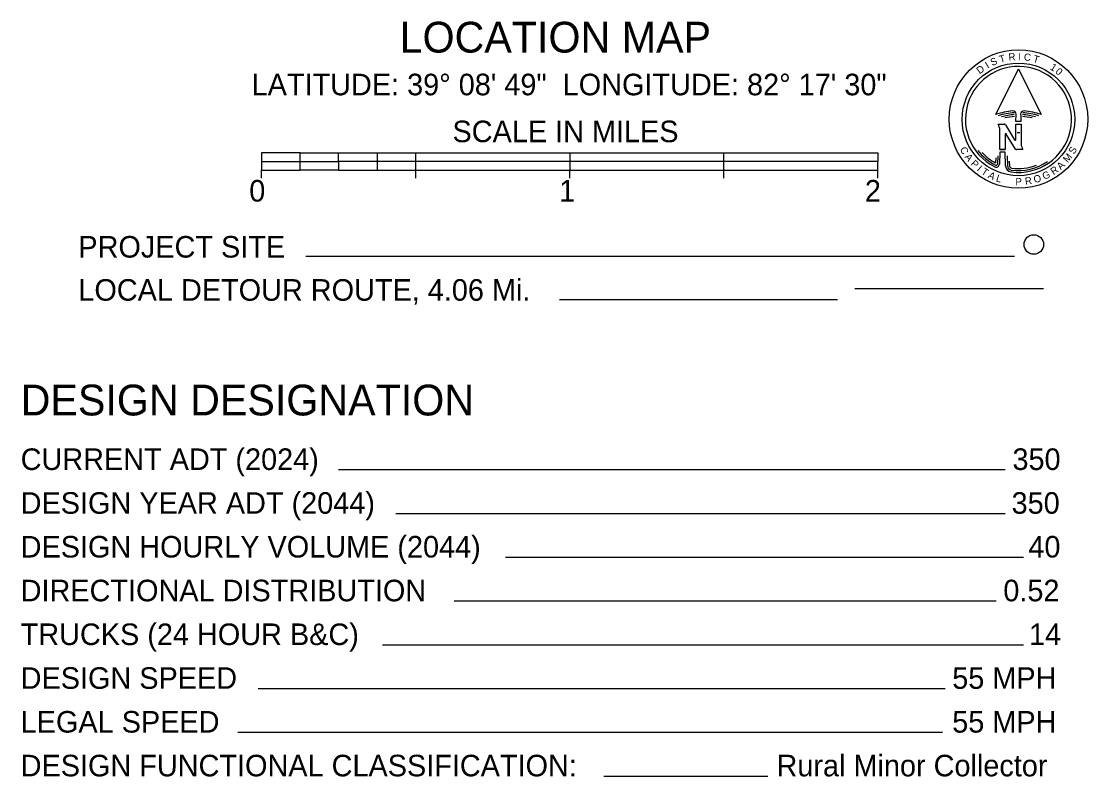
# Model space of a CAD drawing. Extents: x -15 to 405, y -40 to 87.
# Drawn here: x 32.612 to 36.073, y -34.788 to -32.337 of the extents above; entities that cross this region are included whole.
import ezdxf

# ---------------------------------------------------------------- set-up
doc = ezdxf.new("R2010")
doc.units = 0
for name, color, linetype in [('GM_P_State_Shield', 7, 'Continuous'), ('GM_X_Township', 7, 'Continuous'), ('GM_X_Township_ROW', 7, 'Continuous')]:
    doc.layers.add(name, color=color, linetype=linetype)

msp = doc.modelspace()

# ---------------------------------------------------------------- linework, layer by layer
at = {"layer": 'GM_P_State_Shield'}
msp.add_line((35.9294, -33.2052), (35.3172, -33.2052), dxfattribs=at)
at = {"layer": 'GM_X_Township'}
for p, q in [((35.7747, -32.639), (35.848, -32.4902)), ((35.848, -32.4902), (35.9212, -32.639)), ((35.8397, -32.6618), (35.8406, -32.6379)), ((35.856, -32.6618), (35.8397, -32.6618)), ((35.848, -32.6549), (35.848, -32.6549)), ((35.848, -32.6549), (35.848, -32.6549)), ((35.848, -32.6549), (35.848, -32.6549)), ((35.848, -32.6549), (35.848, -32.6549)), ((35.7816, -32.6701), (35.8025, -32.6701)), ((35.7878, -32.753), (35.7878, -32.6888)), ((35.806, -32.6721), (35.8355, -32.7208)), ((35.8394, -32.7198), (35.8394, -32.6701)), ((35.8394, -32.6701), (35.8564, -32.6701)), ((35.8564, -32.6701), (35.8564, -32.7344)), ((35.8048, -32.7034), (35.8048, -32.753)), ((35.8382, -32.7511), (35.8086, -32.7024)), ((35.8523, -32.6987), (35.8437, -32.6987)), ((33.5171, -32.7632), (33.3921, -32.7632)), ((33.3921, -32.7632), (33.3921, -32.7913)), ((33.5171, -32.7632), (33.6421, -32.7632)), ((33.5171, -32.7913), (33.5171, -32.7632)), ((33.6421, -32.7913), (33.6421, -32.7632)), ((33.6421, -32.7632), (33.7671, -32.7632)), ((33.7671, -32.7632), (33.8921, -32.7632)), ((33.7671, -32.7632), (33.7671, -32.7913)), ((33.8921, -32.7913), (33.8921, -32.7632)), ((33.8921, -32.7632), (34.3921, -32.7632)), ((34.3921, -32.7632), (34.8921, -32.7632)), ((34.3921, -32.7632), (34.3921, -32.7913)), ((34.8921, -32.7913), (34.8921, -32.7632)), ((34.8921, -32.7632), (35.3921, -32.7632)), ((35.3921, -32.7632), (35.3921, -32.7913)), ((35.7878, -32.7613), (35.786, -32.8001)), ((35.8048, -32.753), (35.7878, -32.753)), ((35.7878, -32.753), (35.8048, -32.753)), ((35.8048, -32.7613), (35.7878, -32.7613)), ((35.8061, -32.806), (35.8048, -32.7613)), ((35.8626, -32.753), (35.8417, -32.753)), ((33.3921, -32.7913), (33.3921, -32.8194)), ((33.3921, -32.7913), (33.5171, -32.7913)), ((33.5171, -32.7913), (33.6421, -32.7913)), ((33.5171, -32.8194), (33.5171, -32.7913)), ((33.6421, -32.7913), (33.6421, -32.8194)), ((33.7671, -32.7913), (33.6421, -32.7913)), ((33.8921, -32.7913), (33.7671, -32.7913)), ((33.7671, -32.7913), (33.7671, -32.8194)), ((33.8921, -32.8194), (33.8921, -32.7913)), ((34.3921, -32.7913), (33.8921, -32.7913)), ((34.8921, -32.7913), (34.3921, -32.7913)), ((34.3921, -32.7913), (34.3921, -32.8194)), ((34.8921, -32.8194), (34.8921, -32.7913)), ((35.3921, -32.7913), (34.8921, -32.7913)), ((35.3921, -32.8194), (35.3921, -32.7913)), ((35.7745, -32.7801), (35.7738, -32.7961)), ((35.781, -32.7732), (35.7798, -32.7996)), ((35.8114, -32.7735), (35.8123, -32.805)), ((35.8181, -32.7903), (35.8185, -32.8049)), ((33.3921, -32.8194), (33.5171, -32.8194)), ((33.3921, -32.8459), (33.3921, -32.8194)), ((33.6421, -32.8194), (33.5171, -32.8194)), ((33.6421, -32.8194), (33.7671, -32.8194)), ((33.7671, -32.8194), (33.8921, -32.8194)), ((33.8921, -32.8194), (34.3921, -32.8194)), ((33.8921, -32.8459), (33.8921, -32.8194)), ((34.3921, -32.8194), (34.8921, -32.8194)), ((34.3921, -32.8459), (34.3921, -32.8194)), ((34.8921, -32.8194), (35.3921, -32.8194)), ((34.8921, -32.8459), (34.8921, -32.8194)), ((35.3921, -32.8459), (35.3921, -32.8194)), ((35.8356, -33.1002), (33.5359, -33.1002)), ((35.2608, -33.2402), (34.3583, -33.2402)), ((35.8048, -33.7926), (33.6421, -33.7926)), ((35.8048, -33.9347), (33.8272, -33.9347)), ((35.8641, -34.0767), (34.183, -34.0767)), ((35.7752, -34.2188), (34.0169, -34.2188)), ((35.8641, -34.3608), (33.7845, -34.3608)), ((35.6101, -34.5028), (33.3812, -34.5028)), ((35.6016, -34.6449), (33.3148, -34.6449)), ((35.0345, -34.7869), (34.5026, -34.7869))]:
    msp.add_line(p, q, dxfattribs=at)
for centre, radius in [((35.848, -32.6538), 0.2246), ((35.848, -32.6549), 0.1827)]:
    msp.add_circle(centre, radius, dxfattribs=at)
for centre, radius, start, end in [((35.848, -32.6549), 0.172, 261.9368, 243.4209), ((35.848, -32.8453), 0.2188, 94.8642, 109.5471), ((35.8303, -32.6375), 0.0104, 357.7797, 94.8642), ((35.8654, -32.6375), 0.0104, 85.1955, 182.1238), ((35.848, -32.8453), 0.2188, 70.4527, 85.1955), ((35.848, -32.8453), 0.2126, 93.7383, 108.099), ((35.848, -32.8453), 0.2064, 93.7383, 105.4967), ((35.848, -32.8453), 0.2002, 93.7383, 102.7576), ((40.6102, -32.4616), 4.7584, 182.1238, 182.4121), ((35.848, -32.8453), 0.2002, 77.2424, 86.2614), ((35.848, -32.8453), 0.2064, 74.5033, 86.2614), ((35.848, -32.8453), 0.2126, 71.901, 86.2614), ((35.7386, -32.6948), 0.0496, 7.0013, 29.8686), ((35.8025, -32.6743), 0.00415, 31.2473, 90), ((35.8069, -32.7034), 0.00207, 31.2462, 180), ((35.8373, -32.7198), 0.00207, 211.2462, 0), ((35.848, -32.6549), 0.1658, 217.2752, 243.4208), ((35.848, -32.6549), 0.1595, 222.5664, 242.2942), ((35.8417, -32.7489), 0.00415, 211.2473, 270), ((35.9056, -32.7283), 0.0496, 187.0013, 209.8686), ((35.7757, -32.7994), 0.0104, 243.4209, 356.2651), ((35.7757, -32.7994), 0.00415, 243.4208, 357.3129), ((35.848, -32.6549), 0.1658, 261.9411, 304.8168), ((35.8268, -32.8046), 0.0207, 183.8064, 261.9368), ((35.8268, -32.8046), 0.0145, 181.6386, 261.9411), ((35.8268, -32.8046), 0.00829, 181.6373, 261.9394), ((35.848, -32.6549), 0.1595, 261.9394, 291.3169)]:
    msp.add_arc(centre, radius, start, end, dxfattribs=at)
at = {"layer": 'GM_X_Township_ROW'}
msp.add_circle((35.8977, -33.0608), 0.0317, dxfattribs=at)

# ---------------------------------------------------------------- texts
at = {"layer": 'GM_X_Township'}
for s, height, p in [('LOCATION MAP', 0.1, (33.8399, -32.438)), ('LATITUDE: 39° 08\' 49"  LONGITUDE: 82° 17\' 30"', 0.07, (33.3597, -32.5766)), ('SCALE IN MILES', 0.07, (34.0115, -32.7288)), ('0', 0.07, (33.352, -32.9215)), ('1', 0.07, (34.3573, -32.9215)), ('2', 0.07, (35.3496, -32.9215)), ('PROJECT SITE', 0.07, (32.7975, -33.1033)), ('LOCAL DETOUR ROUTE, 4.06 Mi.', 0.07, (32.7975, -33.2433)), ('DESIGN DESIGNATION', 0.1, (32.6103, -33.6156)), ('CURRENT ADT (2024)', 0.07, (32.6103, -33.7926)), ('350', 0.07, (35.8285, -33.7926)), ('DESIGN YEAR ADT (2044)', 0.07, (32.6103, -33.9347)), ('350', 0.07, (35.8257, -33.9347)), ('DESIGN HOURLY VOLUME (2044)', 0.07, (32.6103, -34.0767)), ('40', 0.07, (35.8801, -34.0767)), ('DIRECTIONAL DISTRIBUTION', 0.07, (32.6103, -34.2188)), ('0.52', 0.07, (35.7989, -34.2188)), ('TRUCKS (24 HOUR B&C)', 0.07, (32.6103, -34.3608)), ('14', 0.07, (35.8822, -34.3608)), ('DESIGN SPEED', 0.07, (32.6103, -34.5028)), ('55 MPH', 0.07, (35.6331, -34.5028)), ('LEGAL SPEED', 0.07, (32.6103, -34.6449)), ('55 MPH', 0.07, (35.6331, -34.6449)), ('DESIGN FUNCTIONAL CLASSIFICATION:', 0.07, (32.6103, -34.7869)), ('Rural Minor Collector', 0.07, (35.0629, -34.7869))]:
    msp.add_text(s, height=height, dxfattribs=at).set_placement(p)
for s, rotation, p in [('S', 25.6209, (35.7635, -32.4822)), ('T', 15.1852, (35.7891, -32.4716)), ('R', 4.7494, (35.8167, -32.4645)), ('I', 359.5315, (35.8475, -32.4626)), ('C', 354.3137, (35.8648, -32.4633)), ('T', 343.8779, (35.8934, -32.4679)), ('D', 36.0567, (35.7221, -32.5089)), ('I', 30.8388, (35.7483, -32.4906)), ('1', 328.2243, (35.9484, -32.4911)), ('0', 317.7885, (35.9656, -32.5023)), ('C', 298.5647, (35.6568, -32.7514)), ('M', 49.8948, (36.0078, -32.7971)), ('S', 59.6056, (36.0288, -32.7696)), ('A', 307.9093, (35.672, -32.777)), ('P', 317.4317, (35.6912, -32.8011)), ('A', 44.6769, (35.9854, -32.8197)), ('I', 319.1994, (35.7113, -32.8193)), ('T', 327.4133, (35.725, -32.8299)), ('A', 332.6312, (35.7471, -32.8432)), ('L', 343.067, (35.7734, -32.8554)), ('O', 19.5921, (35.9017, -32.8624)), ('G', 24.81, (35.9317, -32.8515)), ('R', 35.2457, (35.9619, -32.836)), ('P', 0.272, (35.8382, -32.8684)), ('R', 9.1564, (35.8709, -32.8674))]:
    msp.add_text(s, height=0.0233, rotation=rotation, dxfattribs=at).set_placement(p)

doc.saveas('drawing.dxf')
